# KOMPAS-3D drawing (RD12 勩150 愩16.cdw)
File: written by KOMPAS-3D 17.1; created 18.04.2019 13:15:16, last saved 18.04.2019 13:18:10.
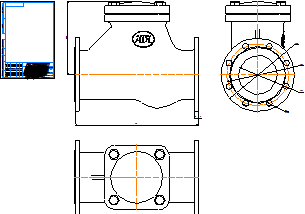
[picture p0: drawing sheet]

Sheet 1: A4, portrait

Title block, sheet 1: name: RD12 Ду150 Ру16; material: Внимание! Данный продукт является объектом авторского права ООО «Торговый Дом АДЛ». / Запрещается изменение, копирование, распространение / (в том числе путем копирования на другие сайты и ресурсы в Интернете) / или любое иное использование информации и объектов без предварительного / согласия правообладателя (ООО «Торговый Дом АДЛ»).; mass: 181,76; sheets: 1; organisation: ООО "Торговый дом АДЛ"; sheet format: A4

Views: Вид 1, Проекционный вид 2, Проекционный вид 3
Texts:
  user
Dimensions and other numbers on the sheet: 285; 16; 3; 474; 240; 150; 23; 8 отв.; 1:1; 1; 181,76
